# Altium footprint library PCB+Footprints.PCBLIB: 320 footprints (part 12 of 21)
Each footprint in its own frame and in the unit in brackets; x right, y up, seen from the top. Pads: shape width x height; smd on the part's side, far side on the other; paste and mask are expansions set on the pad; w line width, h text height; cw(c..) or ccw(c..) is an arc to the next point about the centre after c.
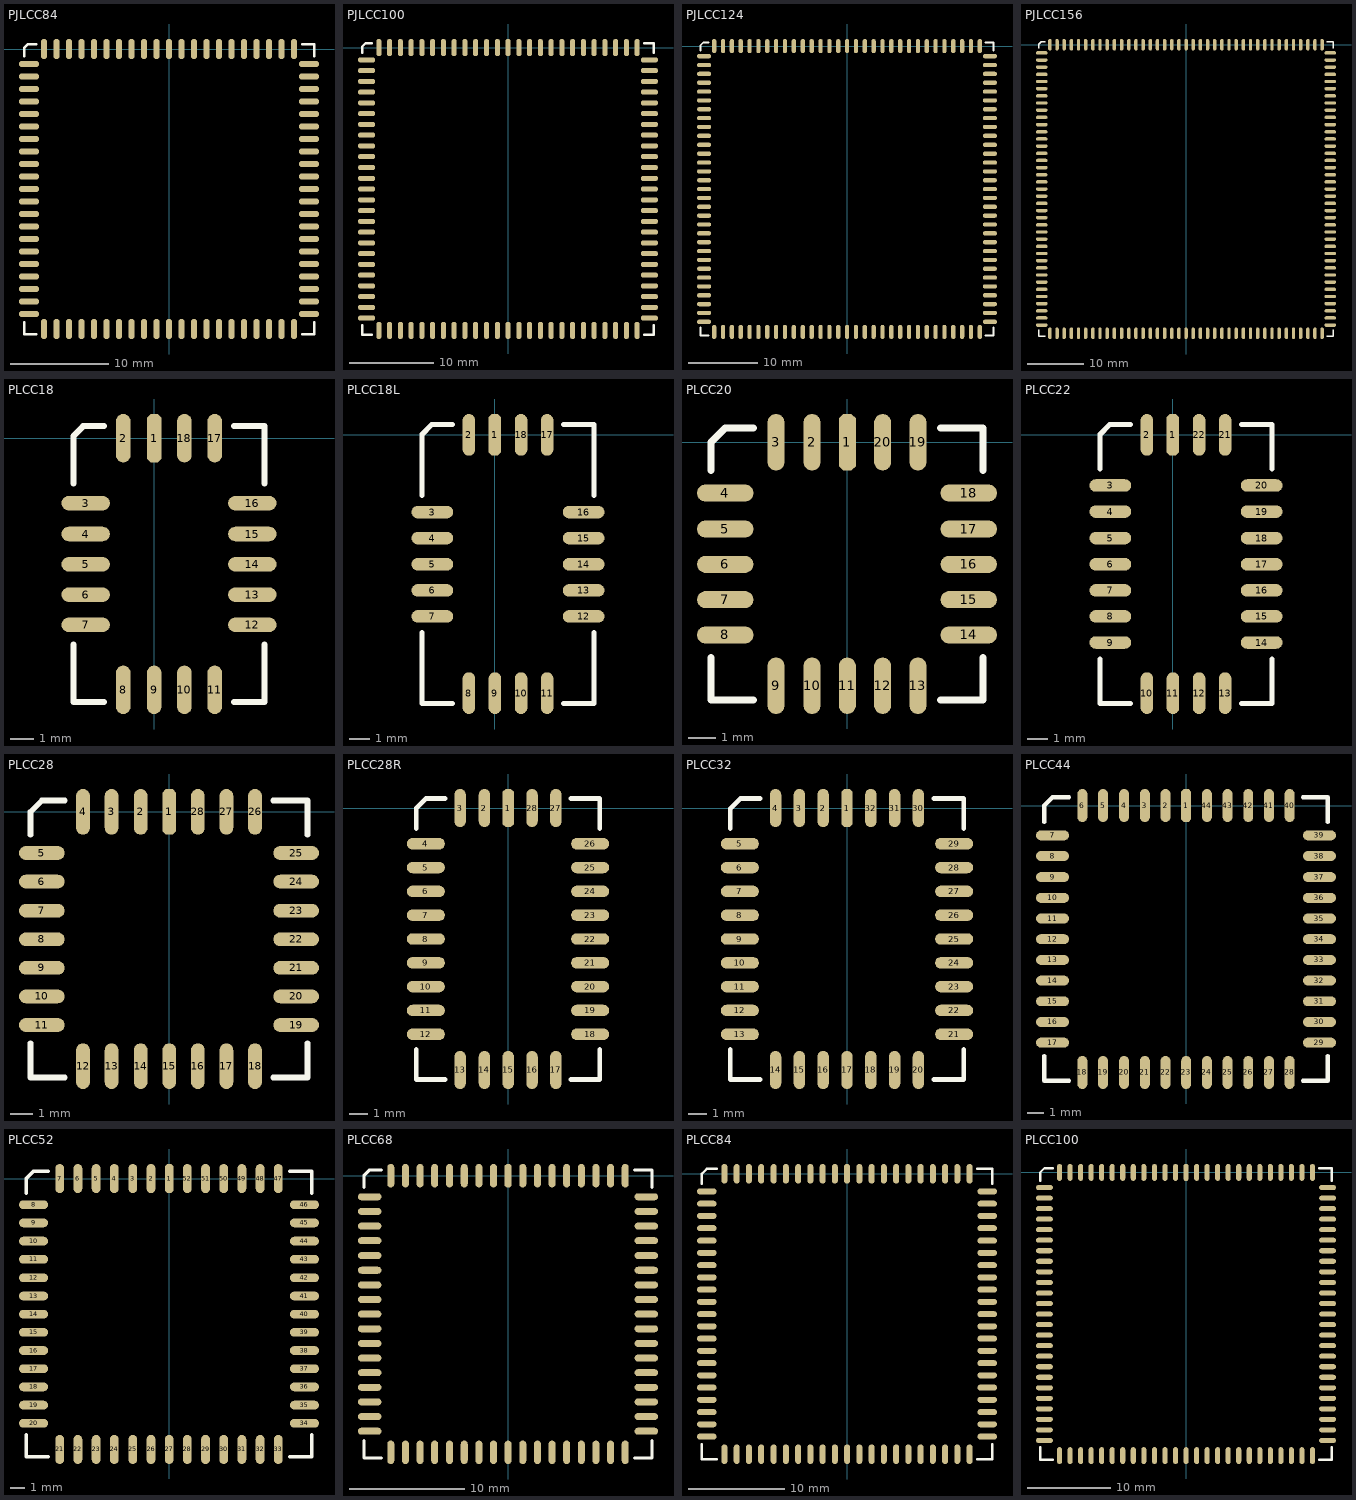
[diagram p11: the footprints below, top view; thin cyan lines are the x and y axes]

## PJLCC84 [mil]
pads (84):
  oct 24x80 smd: 1(0,0)
  oval 24x80 smd: 2(-50,0) 3(-100,0) 4(-150,0) 5(-200,0) 6(-250,0) 7(-300,0) 8(-350,0) 9(-400,0) 10(-450,0) 11(-500,0) 33(-500,-1120) 34(-450,-1120) 35(-400,-1120) 36(-350,-1120) 37(-300,-1120) 38(-250,-1120) 39(-200,-1120) 40(-150,-1120) 41(-100,-1120) 42(-50,-1120) 43(0,-1120) 44(50,-1120) 45(100,-1120) 46(150,-1120) 47(200,-1120) 48(250,-1120) 49(300,-1120) 50(350,-1120) 51(400,-1120) 52(450,-1120) 53(500,-1120) 75(500,0) 76(450,0) 77(400,0) 78(350,0) 79(300,0) 80(250,0) 81(200,0) 82(150,0) 83(100,0) 84(50,0)
  oval 80x24 smd: 12(-560,-60) 13(-560,-110) 14(-560,-160) 15(-560,-210) 16(-560,-260) 17(-560,-310) 18(-560,-360) 19(-560,-410) 20(-560,-460) 21(-560,-510) 22(-560,-560) 23(-560,-610) 24(-560,-660) 25(-560,-710) 26(-560,-760) 27(-560,-810) 28(-560,-860) 29(-560,-910) 30(-560,-960) 31(-560,-1010) 32(-560,-1060) 54(560,-1060) 55(560,-1010) 56(560,-960) 57(560,-910) 58(560,-860) 59(560,-810) 60(560,-760) 61(560,-710) 62(560,-660) 63(560,-610) 64(560,-560) 65(560,-510) 66(560,-460) 67(560,-410) 68(560,-360) 69(560,-310) 70(560,-260) 71(560,-210) 72(560,-160) 73(560,-110) 74(560,-60)
TopOverlay:
  lines w10: -580,-1092 -580,-1140 -532,-1140 ; -580,-28 -580,4 -564,20 -532,20 ; 532,-1140 580,-1140 580,-1092 ; 532,20 580,20 580,-28

## PJLCC100 [mil]
pads (100):
  oct 24x80 smd: 1(0,0)
  oval 24x80 smd: 2(-50,0) 3(-100,0) 4(-151,0) 5(-201,0) 6(-251,0) 7(-301,0) 8(-351,0) 9(-401,0) 10(-451,0) 11(-501,0) 12(-551,0) 13(-601,0) 39(-601,-1315) 40(-551,-1315) 41(-501,-1315) 42(-451,-1315) 43(-401,-1315) 44(-351,-1315) 45(-301,-1315) 46(-251,-1315) 47(-201,-1315) 48(-151,-1315) 49(-100,-1315) 50(-50,-1315) 51(0,-1315) 52(50,-1315) 53(100,-1315) 54(150,-1315) 55(200,-1315) 56(250,-1315) 57(300,-1315) 58(350,-1315) 59(400,-1315) 60(450,-1315) 61(500,-1315) 62(550,-1315) 63(600,-1315) 89(600,0) 90(550,0) 91(500,0) 92(450,0) 93(400,0) 94(350,0) 95(300,0) 96(250,0) 97(200,0) 98(150,0) 99(100,0) 100(50,0)
  oval 80x24 smd: 14(-658,-57) 15(-658,-107) 16(-658,-157) 17(-658,-207) 18(-658,-257) 19(-658,-307) 20(-658,-357) 21(-658,-407) 22(-658,-457) 23(-658,-507) 24(-658,-558) 25(-658,-608) 26(-658,-658) 27(-658,-708) 28(-658,-758) 29(-658,-808) 30(-658,-858) 31(-658,-908) 32(-658,-958) 33(-658,-1008) 34(-658,-1058) 35(-658,-1108) 36(-658,-1158) 37(-658,-1208) 38(-658,-1258) 64(657,-1258) 65(657,-1208) 66(657,-1158) 67(657,-1108) 68(657,-1058) 69(657,-1008) 70(657,-958) 71(657,-908) 72(657,-858) 73(657,-808) 74(657,-758) 75(657,-708) 76(657,-658) 77(657,-608) 78(657,-558) 79(657,-507) 80(657,-457) 81(657,-407) 82(657,-357) 83(657,-307) 84(657,-257) 85(657,-207) 86(657,-157) 87(657,-107) 88(657,-57)
TopOverlay:
  lines w10: -678,-1290 -678,-1335 -633,-1335 ; -678,-25 -678,5 -663,20 -633,20 ; 632,-1335 677,-1335 677,-1290 ; 632,20 677,20 677,-25

## PJLCC124 [mil]
pads (124):
  oct 24x80 smd: 1(0,0)
  oval 24x80 smd: 2(-50,0) 3(-100,0) 4(-150,0) 5(-200,0) 6(-250,0) 7(-301,0) 8(-351,0) 9(-401,0) 10(-451,0) 11(-501,0) 12(-551,0) 13(-601,0) 14(-651,0) 15(-701,0) 16(-751,0) 48(-751,-1615) 49(-701,-1615) 50(-651,-1615) 51(-601,-1615) 52(-551,-1615) 53(-501,-1615) 54(-451,-1615) 55(-401,-1615) 56(-351,-1615) 57(-301,-1615) 58(-250,-1615) 59(-200,-1615) 60(-150,-1615) 61(-100,-1615) 62(-50,-1615) 63(0,-1615) 64(50,-1615) 65(100,-1615) 66(150,-1615) 67(200,-1615) 68(250,-1615) 69(300,-1615) 70(350,-1615) 71(400,-1615) 72(450,-1615) 73(500,-1615) 74(550,-1615) 75(600,-1615) 76(650,-1615) 77(700,-1615) 78(750,-1615) 110(750,0) 111(700,0) 112(650,0) 113(600,0) 114(550,0) 115(500,0) 116(450,0) 117(400,0) 118(350,0) 119(300,0) 120(250,0) 121(200,0) 122(150,0) 123(100,0) 124(50,0)
  oval 80x24 smd: 17(-808,-57) 18(-808,-107) 19(-808,-157) 20(-808,-207) 21(-808,-257) 22(-808,-307) 23(-808,-357) 24(-808,-407) 25(-808,-457) 26(-808,-507) 27(-808,-558) 28(-808,-608) 29(-808,-658) 30(-808,-708) 31(-808,-758) 32(-808,-808) 33(-808,-858) 34(-808,-908) 35(-808,-958) 36(-808,-1008) 37(-808,-1058) 38(-808,-1108) 39(-808,-1158) 40(-808,-1208) 41(-808,-1258) 42(-808,-1308) 43(-808,-1358) 44(-808,-1408) 45(-808,-1458) 46(-808,-1508) 47(-808,-1558) 79(807,-1558) 80(807,-1508) 81(807,-1458) 82(807,-1408) 83(807,-1358) 84(807,-1308) 85(807,-1258) 86(807,-1208) 87(807,-1158) 88(807,-1108) 89(807,-1058) 90(807,-1008) 91(807,-958) 92(807,-908) 93(807,-858) 94(807,-808) 95(807,-758) 96(807,-708) 97(807,-658) 98(807,-608) 99(807,-558) 100(807,-507) 101(807,-457) 102(807,-407) 103(807,-357) 104(807,-307) 105(807,-257) 106(807,-207) 107(807,-157) 108(807,-107) 109(807,-57)
TopOverlay:
  lines w10: -828,-1590 -828,-1635 -783,-1635 ; -828,-25 -828,5 -813,20 -783,20 ; 782,-1635 827,-1635 827,-1590 ; 782,20 827,20 827,-25

## PJLCC156 [mil]
pads (156):
  oct 24x80 smd: 1(0,0)
  oval 24x80 smd: 2(-50,0) 3(-100,0) 4(-150,0) 5(-200,0) 6(-250,0) 7(-300,0) 8(-350,0) 9(-400,0) 10(-450,0) 11(-501,0) 12(-551,0) 13(-601,0) 14(-651,0) 15(-701,0) 16(-751,0) 17(-801,0) 18(-851,0) 19(-901,0) 20(-951,0) 60(-951,-2015) 61(-901,-2015) 62(-851,-2015) 63(-801,-2015) 64(-751,-2015) 65(-701,-2015) 66(-651,-2015) 67(-601,-2015) 68(-551,-2015) 69(-501,-2015) 70(-450,-2015) 71(-400,-2015) 72(-350,-2015) 73(-300,-2015) 74(-250,-2015) 75(-200,-2015) 76(-150,-2015) 77(-100,-2015) 78(-50,-2015) 79(0,-2015) 80(50,-2015) 81(100,-2015) 82(150,-2015) 83(200,-2015) 84(250,-2015) 85(300,-2015) 86(350,-2015) 87(400,-2015) 88(450,-2015) 89(500,-2015) 90(550,-2015) 91(600,-2015) 92(650,-2015) 93(700,-2015) 94(750,-2015) 95(800,-2015) 96(850,-2015) 97(900,-2015) 98(950,-2015) 138(950,0) 139(900,0) 140(850,0) 141(800,0) 142(750,0) 143(700,0) 144(650,0) 145(600,0) 146(550,0) 147(500,0) 148(450,0) 149(400,0) 150(350,0) 151(300,0) 152(250,0) 153(200,0) 154(150,0) 155(100,0) 156(50,0)
  oval 80x24 smd: 21(-1008,-57) 22(-1008,-107) 23(-1008,-157) 24(-1008,-207) 25(-1008,-257) 26(-1008,-307) 27(-1008,-357) 28(-1008,-407) 29(-1008,-457) 30(-1008,-507) 31(-1008,-558) 32(-1008,-608) 33(-1008,-658) 34(-1008,-708) 35(-1008,-758) 36(-1008,-808) 37(-1008,-858) 38(-1008,-908) 39(-1008,-958) 40(-1008,-1008) 41(-1008,-1058) 42(-1008,-1108) 43(-1008,-1158) 44(-1008,-1208) 45(-1008,-1258) 46(-1008,-1308) 47(-1008,-1358) 48(-1008,-1408) 49(-1008,-1458) 50(-1008,-1508) 51(-1008,-1558) 52(-1008,-1608) 53(-1008,-1658) 54(-1008,-1708) 55(-1008,-1758) 56(-1008,-1808) 57(-1008,-1858) 58(-1008,-1908) 59(-1008,-1958) 99(1007,-1958) 100(1007,-1908) 101(1007,-1858) 102(1007,-1808) 103(1007,-1758) 104(1007,-1708) 105(1007,-1658) 106(1007,-1608) 107(1007,-1558) 108(1007,-1508) 109(1007,-1458) 110(1007,-1408) 111(1007,-1358) 112(1007,-1308) 113(1007,-1258) 114(1007,-1208) 115(1007,-1158) 116(1007,-1108) 117(1007,-1058) 118(1007,-1008) 119(1007,-958) 120(1007,-908) 121(1007,-858) 122(1007,-808) 123(1007,-758) 124(1007,-708) 125(1007,-658) 126(1007,-608) 127(1007,-558) 128(1007,-507) 129(1007,-457) 130(1007,-407) 131(1007,-357) 132(1007,-307) 133(1007,-257) 134(1007,-207) 135(1007,-157) 136(1007,-107) 137(1007,-57)
TopOverlay:
  lines w10: -1028,-1990 -1028,-2035 -983,-2035 ; -1028,-25 -1028,5 -1013,20 -983,20 ; 982,-2035 1027,-2035 1027,-1990 ; 982,20 1027,20 1027,-25

## PLCC18 [mil]
pads (18):
  oct 24x80 smd: 1(0,0)
  oval 24x80 smd: 2(-51,0) 8(-51,-415) 9(0,-415) 10(50,-415) 11(100,-415) 17(100,0) 18(50,0)
  oval 80x24 smd: 3(-113,-107) 4(-113,-158) 5(-113,-208) 6(-113,-258) 7(-113,-308) 12(162,-308) 13(162,-258) 14(162,-208) 15(162,-158) 16(162,-107)
TopOverlay:
  lines w10: -133,-340 -133,-435 -83,-435 ; -133,-75 -133,4 -117,20 -83,20 ; 132,-435 182,-435 182,-340 ; 132,20 182,20 182,-75

## PLCC18L [mil]
pads (18):
  oct 24x80 smd: 1(0,0)
  oval 24x80 smd: 2(-50,0) 8(-50,-495) 9(0,-495) 10(50,-495) 11(100,-495) 17(100,0) 18(50,0)
  oval 80x24 smd: 3(-120,-148) 4(-120,-198) 5(-120,-248) 6(-120,-298) 7(-120,-348) 12(170,-348) 13(170,-298) 14(170,-248) 15(170,-198) 16(170,-148)
TopOverlay:
  lines w10: -140,-379 -140,-515 -82,-515 ; -140,-116 -140,1 -121,20 -82,20 ; 132,-515 190,-515 190,-379 ; 132,20 190,20 190,-116

## PLCC20 [mil]
pads (20):
  oct 24x80 smd: 1(0,0)
  oval 24x80 smd: 2(-50,0) 3(-101,0) 9(-101,-345) 10(-50,-345) 11(0,-345) 12(50,-345) 13(100,-345) 19(100,0) 20(50,0)
  oval 80x24 smd: 4(-173,-72) 5(-173,-123) 6(-173,-173) 7(-173,-223) 8(-173,-273) 14(172,-273) 15(172,-223) 16(172,-173) 17(172,-123) 18(172,-72)
TopOverlay:
  lines w10: -193,-305 -193,-365 -133,-365 ; -193,-40 -193,0 -173,20 -133,20 ; 132,-365 192,-365 192,-305 ; 132,20 192,20 192,-40

## PLCC22 [mil]
pads (22):
  oct 24x80 smd: 1(0,0)
  oval 24x80 smd: 2(-50,0) 10(-50,-495) 11(0,-495) 12(50,-495) 13(100,-495) 21(100,0) 22(50,0)
  oval 80x24 smd: 3(-120,-97) 4(-120,-147) 5(-120,-198) 6(-120,-248) 7(-120,-298) 8(-120,-348) 9(-120,-398) 14(170,-398) 15(170,-348) 16(170,-298) 17(170,-248) 18(170,-198) 19(170,-147) 20(170,-97)
TopOverlay:
  lines w10: -140,-430 -140,-515 -82,-515 ; -140,-65 -140,1 -121,20 -82,20 ; 132,-515 190,-515 190,-430 ; 132,20 190,20 190,-65

## PLCC28 [mil]
pads (28):
  oct 24x80 smd: 1(0,0)
  oval 24x80 smd: 2(-50,0) 3(-101,0) 4(-151,0) 12(-151,-445) 13(-101,-445) 14(-50,-445) 15(0,-445) 16(50,-445) 17(100,-445) 18(150,-445) 26(150,0) 27(100,0) 28(50,0)
  oval 80x24 smd: 5(-223,-72) 6(-223,-122) 7(-223,-173) 8(-223,-223) 9(-223,-273) 10(-223,-323) 11(-223,-373) 19(222,-373) 20(222,-323) 21(222,-273) 22(222,-223) 23(222,-173) 24(222,-122) 25(222,-72)
TopOverlay:
  lines w10: -243,-405 -243,-465 -183,-465 ; -243,-40 -243,0 -223,20 -183,20 ; 182,-465 242,-465 242,-405 ; 182,20 242,20 242,-40

## PLCC28R [mil]
pads (28):
  oct 24x80 smd: 1(0,0)
  oval 24x80 smd: 2(-50,0) 3(-101,0) 13(-101,-550) 14(-50,-550) 15(0,-550) 16(50,-550) 17(100,-550) 27(100,0) 28(50,0)
  oval 80x24 smd: 4(-173,-75) 5(-173,-125) 6(-173,-175) 7(-173,-225) 8(-173,-275) 9(-173,-325) 10(-173,-375) 11(-173,-425) 12(-173,-475) 18(172,-475) 19(172,-425) 20(172,-375) 21(172,-325) 22(172,-275) 23(172,-225) 24(172,-175) 25(172,-125) 26(172,-75)
TopOverlay:
  lines w10: -193,-507 -193,-570 -133,-570 ; -193,-43 -193,0 -173,20 -133,20 ; 132,-570 192,-570 192,-507 ; 132,20 192,20 192,-43

## PLCC32 [mil]
pads (32):
  oct 24x80 smd: 1(0,0)
  oval 24x80 smd: 2(-50,0) 3(-100,0) 4(-150,0) 14(-150,-550) 15(-100,-550) 16(-50,-550) 17(0,-550) 18(50,-550) 19(100,-550) 20(150,-550) 30(150,0) 31(100,0) 32(50,0)
  oval 80x24 smd: 5(-225,-75) 6(-225,-125) 7(-225,-175) 8(-225,-225) 9(-225,-275) 10(-225,-325) 11(-225,-375) 12(-225,-425) 13(-225,-475) 21(225,-475) 22(225,-425) 23(225,-375) 24(225,-325) 25(225,-275) 26(225,-225) 27(225,-175) 28(225,-125) 29(225,-75)
TopOverlay:
  lines w10: -245,-507 -245,-570 -182,-570 ; -245,-43 -245,-1 -224,20 -182,20 ; 182,-570 245,-570 245,-507 ; 182,20 245,20 245,-43

## PLCC44 [mil]
pads (44):
  oct 24x80 smd: 1(0,0)
  oval 24x80 smd: 2(-50,0) 3(-100,0) 4(-150,0) 5(-201,0) 6(-251,0) 18(-251,-645) 19(-201,-645) 20(-150,-645) 21(-100,-645) 22(-50,-645) 23(0,-645) 24(50,-645) 25(100,-645) 26(150,-645) 27(200,-645) 28(250,-645) 40(250,0) 41(200,0) 42(150,0) 43(100,0) 44(50,0)
  oval 80x24 smd: 7(-323,-72) 8(-323,-122) 9(-323,-173) 10(-323,-223) 11(-323,-273) 12(-323,-323) 13(-323,-373) 14(-323,-423) 15(-323,-473) 16(-323,-523) 17(-323,-573) 29(322,-573) 30(322,-523) 31(322,-473) 32(322,-423) 33(322,-373) 34(322,-323) 35(322,-273) 36(322,-223) 37(322,-173) 38(322,-122) 39(322,-72)
TopOverlay:
  lines w10: -343,-605 -343,-665 -283,-665 ; -343,-40 -343,0 -323,20 -283,20 ; 282,-665 342,-665 342,-605 ; 282,20 342,20 342,-40

## PLCC52 [mil]
pads (52):
  oct 24x80 smd: 1(0,0)
  oval 24x80 smd: 2(-50,0) 3(-100,0) 4(-151,0) 5(-201,0) 6(-251,0) 7(-301,0) 21(-301,-745) 22(-251,-745) 23(-201,-745) 24(-151,-745) 25(-100,-745) 26(-50,-745) 27(0,-745) 28(50,-745) 29(100,-745) 30(150,-745) 31(200,-745) 32(250,-745) 33(300,-745) 47(300,0) 48(250,0) 49(200,0) 50(150,0) 51(100,0) 52(50,0)
  oval 80x24 smd: 8(-373,-72) 9(-373,-122) 10(-373,-172) 11(-373,-222) 12(-373,-273) 13(-373,-323) 14(-373,-373) 15(-373,-423) 16(-373,-473) 17(-373,-523) 18(-373,-573) 19(-373,-623) 20(-373,-673) 34(372,-673) 35(372,-623) 36(372,-573) 37(372,-523) 38(372,-473) 39(372,-423) 40(372,-373) 41(372,-323) 42(372,-273) 43(372,-222) 44(372,-172) 45(372,-122) 46(372,-72)
TopOverlay:
  lines w10: -393,-705 -393,-765 -333,-765 ; -393,-40 -393,0 -373,20 -333,20 ; 332,-765 392,-765 392,-705 ; 332,20 392,20 392,-40

## PLCC68 [mil]
pads (68):
  oct 24x80 smd: 1(0,0)
  oval 24x80 smd: 2(-50,0) 3(-100,0) 4(-150,0) 5(-200,0) 6(-251,0) 7(-301,0) 8(-351,0) 9(-401,0) 27(-401,-945) 28(-351,-945) 29(-301,-945) 30(-251,-945) 31(-200,-945) 32(-150,-945) 33(-100,-945) 34(-50,-945) 35(0,-945) 36(50,-945) 37(100,-945) 38(150,-945) 39(200,-945) 40(250,-945) 41(300,-945) 42(350,-945) 43(400,-945) 61(400,0) 62(350,0) 63(300,0) 64(250,0) 65(200,0) 66(150,0) 67(100,0) 68(50,0)
  oval 80x24 smd: 10(-473,-72) 11(-473,-122) 12(-473,-172) 13(-473,-222) 14(-473,-273) 15(-473,-323) 16(-473,-373) 17(-473,-423) 18(-473,-473) 19(-473,-523) 20(-473,-573) 21(-473,-623) 22(-473,-673) 23(-473,-723) 24(-473,-773) 25(-473,-823) 26(-473,-873) 44(472,-873) 45(472,-823) 46(472,-773) 47(472,-723) 48(472,-673) 49(472,-623) 50(472,-573) 51(472,-523) 52(472,-473) 53(472,-423) 54(472,-373) 55(472,-323) 56(472,-273) 57(472,-222) 58(472,-172) 59(472,-122) 60(472,-72)
TopOverlay:
  lines w10: -493,-905 -493,-965 -433,-965 ; -493,-40 -493,0 -473,20 -433,20 ; 432,-965 492,-965 492,-905 ; 432,20 492,20 492,-40

## PLCC84 [mil]
pads (84):
  oct 24x80 smd: 1(0,0)
  oval 24x80 smd: 2(-50,0) 3(-100,0) 4(-150,0) 5(-200,0) 6(-250,0) 7(-300,0) 8(-351,0) 9(-401,0) 10(-451,0) 11(-501,0) 33(-501,-1145) 34(-451,-1145) 35(-401,-1145) 36(-351,-1145) 37(-300,-1145) 38(-250,-1145) 39(-200,-1145) 40(-150,-1145) 41(-100,-1145) 42(-50,-1145) 43(0,-1145) 44(50,-1145) 45(100,-1145) 46(150,-1145) 47(200,-1145) 48(250,-1145) 49(300,-1145) 50(350,-1145) 51(400,-1145) 52(450,-1145) 53(500,-1145) 75(500,0) 76(450,0) 77(400,0) 78(350,0) 79(300,0) 80(250,0) 81(200,0) 82(150,0) 83(100,0) 84(50,0)
  oval 80x24 smd: 12(-573,-72) 13(-573,-122) 14(-573,-172) 15(-573,-222) 16(-573,-273) 17(-573,-323) 18(-573,-373) 19(-573,-423) 20(-573,-473) 21(-573,-523) 22(-573,-573) 23(-573,-623) 24(-573,-673) 25(-573,-723) 26(-573,-773) 27(-573,-823) 28(-573,-873) 29(-573,-923) 30(-573,-973) 31(-573,-1023) 32(-573,-1073) 54(572,-1073) 55(572,-1023) 56(572,-973) 57(572,-923) 58(572,-873) 59(572,-823) 60(572,-773) 61(572,-723) 62(572,-673) 63(572,-623) 64(572,-573) 65(572,-523) 66(572,-473) 67(572,-423) 68(572,-373) 69(572,-323) 70(572,-273) 71(572,-222) 72(572,-172) 73(572,-122) 74(572,-72)
TopOverlay:
  lines w10: -593,-1105 -593,-1165 -533,-1165 ; -593,-40 -593,0 -573,20 -533,20 ; 532,-1165 592,-1165 592,-1105 ; 532,20 592,20 592,-40

## PLCC100 [mil]
pads (100):
  oct 24x80 smd: 1(0,0)
  oval 24x80 smd: 2(-50,0) 3(-100,0) 4(-150,0) 5(-201,0) 6(-251,0) 7(-301,0) 8(-351,0) 9(-401,0) 10(-451,0) 11(-501,0) 12(-551,0) 13(-601,0) 39(-601,-1345) 40(-551,-1345) 41(-501,-1345) 42(-451,-1345) 43(-401,-1345) 44(-351,-1345) 45(-301,-1345) 46(-251,-1345) 47(-201,-1345) 48(-150,-1345) 49(-100,-1345) 50(-50,-1345) 51(0,-1345) 52(50,-1345) 53(100,-1345) 54(150,-1345) 55(200,-1345) 56(250,-1345) 57(300,-1345) 58(350,-1345) 59(400,-1345) 60(450,-1345) 61(500,-1345) 62(550,-1345) 63(600,-1345) 89(600,0) 90(550,0) 91(500,0) 92(450,0) 93(400,0) 94(350,0) 95(300,0) 96(250,0) 97(200,0) 98(150,0) 99(100,0) 100(50,0)
  oval 80x24 smd: 14(-673,-72) 15(-673,-122) 16(-673,-172) 17(-673,-222) 18(-673,-272) 19(-673,-322) 20(-673,-372) 21(-673,-422) 22(-673,-472) 23(-673,-523) 24(-673,-573) 25(-673,-623) 26(-673,-673) 27(-673,-723) 28(-673,-773) 29(-673,-823) 30(-673,-873) 31(-673,-923) 32(-673,-973) 33(-673,-1023) 34(-673,-1073) 35(-673,-1123) 36(-673,-1173) 37(-673,-1223) 38(-673,-1273) 64(672,-1273) 65(672,-1223) 66(672,-1173) 67(672,-1123) 68(672,-1073) 69(672,-1023) 70(672,-973) 71(672,-923) 72(672,-873) 73(672,-823) 74(672,-773) 75(672,-723) 76(672,-673) 77(672,-623) 78(672,-573) 79(672,-523) 80(672,-472) 81(672,-422) 82(672,-372) 83(672,-322) 84(672,-272) 85(672,-222) 86(672,-172) 87(672,-122) 88(672,-72)
TopOverlay:
  lines w10: -693,-1305 -693,-1365 -633,-1365 ; -693,-40 -693,0 -673,20 -633,20 ; 632,-1365 692,-1365 692,-1305 ; 632,20 692,20 692,-40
